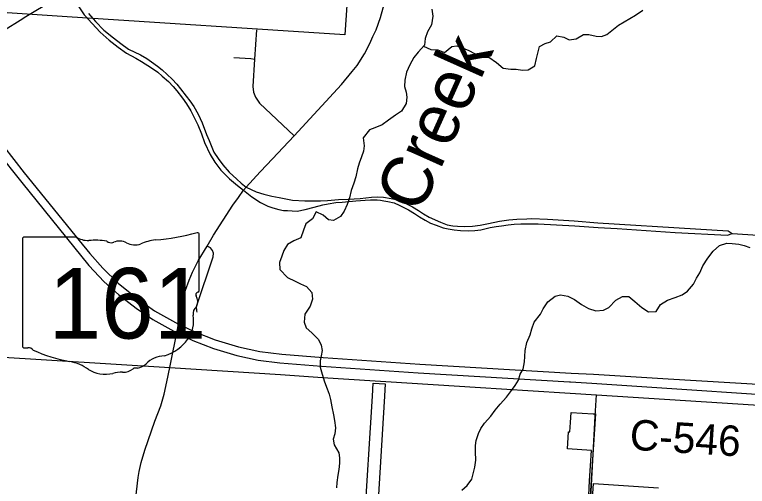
# Model space of a CAD drawing. Extents: x 0 to 91.3, y -0.7 to 22.
# Drawn here: x 3.152 to 4.519, y 17.345 to 18.226 of the extents above; entities that cross this region are included whole.
import ezdxf

# ---------------------------------------------------------------- set-up
doc = ezdxf.new("R2010")
doc.units = 0
for name, color, linetype in [('GM_X_City_Street', 7, 'Continuous'), ('GM_X_Corporation', 7, 'Continuous'), ('GM_X_County_Road', 7, 'Continuous'), ('GM_X_County_Road_Text', 7, 'Continuous'), ('GM_X_Minor_River', 7, 'Continuous'), ('GM_X_Minor_River_Text', 7, 'Continuous'), ('GM_X_State_Location', 7, 'Continuous'), ('GM_X_State_Route', 7, 'Continuous'), ('GM_X_State_Shield', 7, 'Continuous'), ('GM_X_US_Route', 7, 'Continuous')]:
    doc.layers.add(name, color=color, linetype=linetype)

msp = doc.modelspace()

# ---------------------------------------------------------------- linework, layer by layer
at = {"layer": 'GM_X_City_Street'}
for points in [[(3.2718, 18.24), (3.2817, 18.2251), (3.2962, 18.2089), (3.3114, 18.1927), (3.3284, 18.178), (3.3448, 18.1647), (3.3608, 18.1536), (3.378, 18.1446), (3.3883, 18.1384), (3.4075, 18.1265), (3.4188, 18.118), (3.4272, 18.1109), (3.4388, 18.1008), (3.4476, 18.0916), (3.4546, 18.0832), (3.4653, 18.0695), (3.4726, 18.0588), (3.4806, 18.0463), (3.4857, 18.0358), (3.4937, 18.0201), (3.5006, 18.0032), (3.5061, 17.9868), (3.5166, 17.9646), (3.5256, 17.95), (3.5364, 17.9355), (3.553, 17.9189), (3.5677, 17.9069), (3.5786, 17.8977)], [(3.2897, 18.2275), (3.3029, 18.2131), (3.3181, 18.1969), (3.3362, 18.1826), (3.35, 18.1718), (3.3644, 18.1611), (3.3866, 18.1503), (3.3982, 18.1436), (3.4073, 18.1373), (3.4185, 18.1294), (3.4268, 18.1227), (3.4455, 18.105), (3.4543, 18.0958), (3.4613, 18.0874), (3.472, 18.0737), (3.479, 18.0648), (3.4859, 18.0544), (3.494, 18.0396), (3.5017, 18.0234), (3.5099, 18.0018), (3.5148, 17.9906), (3.5233, 17.9688), (3.5318, 17.9573), (3.5405, 17.9453), (3.5523, 17.9317), (3.5661, 17.9183), (3.5744, 17.9111), (3.584, 17.9037), (3.6025, 17.895), (3.6167, 17.8905), (3.6318, 17.8869), (3.6456, 17.8842), (3.6704, 17.8795), (3.6933, 17.8781), (3.7102, 17.8777), (3.7224, 17.8781), (3.7358, 17.8785), (3.7563, 17.8802), (3.7741, 17.881), (3.7963, 17.8822), (3.8178, 17.8848), (3.8294, 17.8856), (3.8398, 17.8848), (3.854, 17.8822), (3.8637, 17.8803), (3.8768, 17.8757), (3.8941, 17.8665), (3.9053, 17.8602), (3.9148, 17.8538), (3.9252, 17.8477), (3.946, 17.8381), (3.9588, 17.8334), (3.9696, 17.8314), (3.9779, 17.8308), (3.9909, 17.8302), (4.0059, 17.8304), (4.0205, 17.8324), (4.036, 17.8355), (4.0561, 17.8397), (4.0738, 17.8422), (4.089, 17.8436), (4.1071, 17.8442), (4.1166, 17.8448), (4.1457, 17.8436), (4.1959, 17.8407), (4.2397, 17.8371), (4.4221, 17.8257), (4.4827, 17.8218), (4.4901, 17.8172)], [(3.6031, 18.1974), (3.5993, 18.1423), (3.5965, 18.0917), (3.5975, 18.0808), (3.6013, 18.0714), (3.6087, 18.0605), (3.6733, 17.9996)], [(3.5606, 18.1459), (3.5926, 18.1436), (3.5993, 18.1423)], [(3.5786, 17.8977), (3.5944, 17.8855), (3.6104, 17.8748), (3.6242, 17.868), (3.6335, 17.8647), (3.645, 17.8617), (3.6537, 17.8601), (3.6606, 17.8596), (3.6696, 17.8592), (3.6787, 17.8588), (3.694, 17.8617), (3.7107, 17.8662), (3.7271, 17.8704), (3.7367, 17.8723), (3.7512, 17.8748), (3.7626, 17.8756), (3.7883, 17.8781), (3.806, 17.8791), (3.8158, 17.8796), (3.8279, 17.8796), (3.8341, 17.8789), (3.8403, 17.8782), (3.8479, 17.8769), (3.8597, 17.8742), (3.869, 17.8701), (3.8863, 17.8609), (3.8975, 17.8546), (3.907, 17.8482), (3.9174, 17.8421), (3.9274, 17.8363), (3.9381, 17.8324), (3.951, 17.8278), (3.9605, 17.8255), (3.9718, 17.8236), (3.9834, 17.8224), (3.9989, 17.8218), (4.0106, 17.8224), (4.0218, 17.824), (4.0392, 17.8279), (4.0502, 17.83), (4.0602, 17.8315), (4.0728, 17.8331), (4.0836, 17.8341), (4.0963, 17.835), (4.1109, 17.8353), (4.1283, 17.8353), (4.1971, 17.8311), (4.2402, 17.8283), (4.2759, 17.826), (4.3843, 17.8191), (4.4819, 17.8141), (4.4901, 17.8172)], [(4.4901, 17.8172), (4.6159, 17.8088), (4.6734, 17.8048), (4.7564, 17.7996)]]:
    msp.add_lwpolyline(points, dxfattribs=at)
at = {"layer": 'GM_X_Corporation'}
msp.add_lwpolyline([(3.8019, 18.6958), (3.7678, 18.1877), (3.2499, 18.2218), (2.7457, 18.2558), (2.7736, 18.7721)], close=True, dxfattribs=at)
for points in [[(3.8037, 17.2665), (3.8193, 17.5135), (3.8209, 17.5377), (3.8322, 17.5369), (3.8433, 17.5362), (3.8419, 17.5135), (3.8279, 17.2882)], [(4.2227, 17.3281), (4.2244, 17.3548), (4.2262, 17.3833), (4.2281, 17.4116), (4.1832, 17.4146), (4.1853, 17.4468), (4.1878, 17.4466), (4.189, 17.4643), (4.1903, 17.4827), (4.2308, 17.4802), (4.2353, 17.48), (4.2258, 17.3279)], [(4.2275, 17.285), (4.2317, 17.3498), (4.3527, 17.3419)]]:
    msp.add_lwpolyline(points, dxfattribs=at)
at = {"layer": 'GM_X_County_Road'}
for p, q in [((3.6476, 17.5534), (3.7262, 17.5483)), ((3.7262, 17.5483), (3.8244, 17.542)), ((3.8244, 17.542), (3.8441, 17.5408)), ((3.8441, 17.5408), (4.0209, 17.5295)), ((4.0209, 17.5295), (4.0602, 17.527)), ((4.0602, 17.527), (4.0701, 17.5263)), ((4.0701, 17.5263), (4.1094, 17.5238)), ((4.1094, 17.5238), (4.188, 17.5188)), ((4.235, 17.4759), (4.2371, 17.5157))]:
    msp.add_line(p, q, dxfattribs=at)
for points in [[(3.6222, 17.9453), (3.6733, 17.9996), (3.7616, 18.0953), (3.7814, 18.1194), (3.7906, 18.1309), (3.8043, 18.1522), (3.8145, 18.1715), (3.8203, 18.1847), (3.8262, 18.1972), (3.8345, 18.2206), (3.846, 18.2638), (3.8752, 18.3822), (3.908, 18.5219), (3.9227, 18.5819), (3.9334, 18.627), (3.9497, 18.6887)], [(3.4432, 17.5763), (3.4545, 17.6317), (3.4576, 17.6479), (3.4634, 17.6779), (3.4708, 17.7113), (3.4773, 17.73), (3.4838, 17.745), (3.4941, 17.7661), (3.511, 17.7932), (3.5229, 17.8138), (3.5587, 17.8699), (3.5694, 17.8844), (3.5786, 17.8977), (3.584, 17.9037), (3.6098, 17.9322), (3.6222, 17.9453)], [(3.4923, 17.6701), (3.4916, 17.6728), (3.4912, 17.6809), (3.5224, 17.7736), (3.5226, 17.7805), (3.5211, 17.7853), (3.5173, 17.7899), (3.511, 17.7932)], [(2.7141, 17.6125), (2.7707, 17.6087), (3.4412, 17.5665), (3.6476, 17.5534)], [(3.3762, 17.3079), (3.3826, 17.361), (3.3844, 17.3728), (3.3881, 17.3893), (3.3947, 17.4123), (3.4133, 17.4666), (3.4243, 17.4954), (3.4308, 17.5171), (3.4361, 17.5397), (3.4412, 17.5665), (3.4432, 17.5763)], [(4.188, 17.5188), (4.2371, 17.5157), (4.5695, 17.4947), (4.592, 17.4929), (4.6804, 17.4873)], [(4.2269, 17.3269), (4.2276, 17.3349), (4.235, 17.4759)]]:
    msp.add_lwpolyline(points, dxfattribs=at)
at = {"layer": 'GM_X_Minor_River'}
for points in [[(3.93, 18.2361), (3.9322, 18.2225), (3.9298, 18.2069), (3.9218, 18.1937), (3.9179, 18.1812), (3.9163, 18.1687), (3.9049, 18.1558), (3.8968, 18.1456), (3.8888, 18.132), (3.8826, 18.1184), (3.8799, 18.1036), (3.8794, 18.0915), (3.8824, 18.0808), (3.8838, 18.0713), (3.8822, 18.0596), (3.8734, 18.0452), (3.8624, 18.0377), (3.8494, 18.0287), (3.8376, 18.02), (3.8239, 18.014), (3.814, 18.0106), (3.8021, 17.9959), (3.8036, 17.9807), (3.8028, 17.9709), (3.7989, 17.9599), (3.7946, 17.9481), (3.7915, 17.9379), (3.7884, 17.9228), (3.7845, 17.911), (3.7795, 17.897), (3.7764, 17.8837), (3.7725, 17.8712), (3.7668, 17.8587), (3.7599, 17.8485), (3.7465, 17.8414), (3.7371, 17.8426), (3.7272, 17.851), (3.7144, 17.8572), (3.7075, 17.8443), (3.6953, 17.8353), (3.6906, 17.8231), (3.6856, 17.8088), (3.673, 17.8035), (3.6609, 17.7964), (3.6543, 17.7854), (3.6501, 17.7748), (3.6462, 17.7627), (3.6469, 17.7498), (3.6609, 17.7349), (3.6749, 17.728), (3.6854, 17.723), (3.6964, 17.718), (3.7062, 17.7069), (3.7077, 17.6944), (3.703, 17.6815), (3.6934, 17.6664), (3.6918, 17.6512), (3.6959, 17.6406), (3.7061, 17.6314), (3.7186, 17.6188), (3.7234, 17.6082), (3.7253, 17.5983), (3.7237, 17.5888), (3.7221, 17.5793), (3.7217, 17.5676), (3.7258, 17.5542), (3.7299, 17.5402), (3.7347, 17.5269), (3.7384, 17.517), (3.741, 17.5071), (3.7436, 17.4934), (3.7465, 17.4782), (3.7488, 17.468), (3.7502, 17.4543), (3.7494, 17.4429), (3.7459, 17.4331), (3.7477, 17.422), (3.7564, 17.4076), (3.7582, 17.3981), (3.7581, 17.3878), (3.7565, 17.3761), (3.7549, 17.3655), (3.753, 17.3518), (3.7525, 17.3419)], [(3.9146, 18.1668), (3.928, 18.1603), (3.9413, 18.1602), (3.9538, 18.1548), (3.9672, 18.1661), (3.977, 18.1672), (3.9869, 18.1637), (3.9982, 18.1591), (4.0107, 18.1522), (4.0236, 18.146), (4.0365, 18.146), (4.0505, 18.1364), (4.0633, 18.1257), (4.0777, 18.1241), (4.0876, 18.124), (4.0993, 18.1221), (4.11, 18.1224), (4.1222, 18.1303), (4.1253, 18.1439), (4.1284, 18.156), (4.1311, 18.1663), (4.1418, 18.1719), (4.1513, 18.1749), (4.1631, 18.1862), (4.1764, 18.1838), (4.1862, 18.1788), (4.1995, 18.1807), (4.2132, 18.1885), (4.2231, 18.1885), (4.2367, 18.1854), (4.2466, 18.1846), (4.2565, 18.1887), (4.266, 18.1958), (4.2782, 18.206), (4.2889, 18.2124), (4.2992, 18.2184), (4.3099, 18.2244), (4.3236, 18.2342)], [(3.9859, 17.3379), (3.9958, 17.3462), (4.0046, 17.3583), (4.0081, 17.3704), (4.0105, 17.3806), (4.0121, 17.3939), (4.0114, 17.4091), (4.0119, 17.4209), (4.0131, 17.4303), (4.0173, 17.4432), (4.0215, 17.4531), (4.0284, 17.4629), (4.0399, 17.4761), (4.0483, 17.4871), (4.0575, 17.4984), (4.0697, 17.5112), (4.077, 17.521), (4.0858, 17.5331), (4.0916, 17.543), (4.0947, 17.554), (4.1004, 17.5638), (4.1028, 17.5774), (4.1036, 17.5873), (4.1044, 17.5983), (4.1072, 17.6131), (4.1133, 17.6275), (4.1164, 17.6388), (4.1211, 17.6513), (4.1326, 17.6661), (4.1379, 17.6763), (4.1467, 17.6891), (4.1605, 17.6997), (4.17, 17.7023), (4.1836, 17.6999), (4.1961, 17.6934), (4.2093, 17.6846), (4.2226, 17.6769), (4.2358, 17.6727), (4.2503, 17.6737), (4.2605, 17.679), (4.2735, 17.6926), (4.2861, 17.6993), (4.2975, 17.6996), (4.3088, 17.6901), (4.3216, 17.6786), (4.3345, 17.6706), (4.3485, 17.6712), (4.3566, 17.6841), (4.3695, 17.6924), (4.384, 17.6976), (4.3973, 17.7025), (4.4072, 17.7092), (4.4183, 17.7221), (4.4241, 17.7334), (4.4298, 17.7433), (4.4356, 17.7565), (4.4448, 17.7712), (4.4547, 17.7837), (4.467, 17.7946), (4.4806, 17.7987), (4.4905, 17.7983), (4.5027, 17.7971), (4.5125, 17.7944), (4.5231, 17.7909)]]:
    msp.add_lwpolyline(points, dxfattribs=at)
at = {"layer": 'GM_X_State_Route'}
for p, q in [((4.2316, 17.554), (4.3709, 17.5457)), ((4.2287, 17.5374), (4.3685, 17.528))]:
    msp.add_line(p, q, dxfattribs=at)
for points in [[(2.8069, 18.2433), (2.8463, 18.2248), (2.861, 18.2175), (2.8955, 18.1979), (2.9278, 18.1775), (2.9626, 18.1534), (3.0059, 18.1177), (3.0269, 18.0986), (3.0497, 18.0763), (3.0703, 18.0541), (3.0936, 18.0267), (3.1309, 17.9799), (3.1699, 17.9304), (3.2723, 17.8036), (3.2921, 17.7795), (3.3166, 17.7521), (3.3451, 17.7242), (3.3799, 17.696), (3.413, 17.6724), (3.4576, 17.6479), (3.4647, 17.6445)], [(2.9789, 18.1194), (2.9918, 18.1088), (3.0113, 18.0915), (3.0344, 18.0696), (3.0545, 18.0483), (3.0776, 18.0218), (3.1082, 17.9831), (3.1181, 17.9709), (3.1651, 17.9123), (3.2903, 17.7575), (3.3188, 17.727), (3.3458, 17.7031), (3.3783, 17.6776), (3.4099, 17.6561), (3.4545, 17.6317), (3.4571, 17.6304)], [(3.4647, 17.6445), (3.4878, 17.6331), (3.5262, 17.6184), (3.5696, 17.6055), (3.6093, 17.5967), (3.6501, 17.5915), (3.7275, 17.5855), (3.9079, 17.573), (4.1898, 17.5564), (4.2316, 17.554)], [(3.4571, 17.6304), (3.4846, 17.6169), (3.523, 17.6022), (3.5665, 17.5892), (3.6062, 17.5805), (3.6469, 17.5752), (3.7244, 17.5693), (3.9047, 17.5568), (4.1867, 17.5402), (4.1887, 17.5401), (4.2287, 17.5374)], [(4.3709, 17.5457), (4.549, 17.5351), (4.7393, 17.5249)], [(4.3685, 17.528), (4.5543, 17.5156), (4.7383, 17.5089)]]:
    msp.add_lwpolyline(points, dxfattribs=at)
at = {"layer": 'GM_X_State_Shield'}
for p, q in [((3.2664, 17.8103), (3.1699, 17.8103)), ((3.4963, 17.7105), (3.4963, 17.8152)), ((3.1667, 17.8068), (3.1667, 17.6067)), ((3.4962, 17.7106), (3.4963, 17.7105))]:
    msp.add_line(p, q, dxfattribs=at)
for centre, major_axis, start_param, end_param in [((3.1705, 17.8072), (0.00382, 0), 1.712693, 3.28349), ((3.2894, 17.8335), (0.037, 0), 4.042523, 4.731795), ((3.3789, 18.0831), (0.3495, 0), 4.814394, 5.042369), ((3.4926, 17.8156), (0.00367, 0), 6.141152, 7.989035), ((3.3017, 17.6979), (0.133, 0), 1.404758, 1.657858), ((3.3319, 17.8083), (0.0107, 0), 3.836095, 5.185415), ((3.3476, 17.7851), (0.0222, 0), 0.950623, 2.079405), ((3.3762, 17.8169), (0.0267, 0), 4.081561, 5.145723), ((3.4234, 17.7491), (0.0703, 0), 1.699011, 2.107814), ((3.4954, 17.7028), (0.00568, 0), 1.883978, 3.671073), ((3.4593, 17.6896), (0.0341, 0), 5.934695, 6.695948), ((3.4923, 17.7101), (0.00393, 0), 5.05454, 6.418171), ((3.5094, 17.6667), (0.0248, 0), 2.387724, 3.262537), ((3.3984, 17.6534), (0.0874, 0), 5.101752, 6.440018), ((3.1705, 17.6063), (0.00385, 0), 3.00124, 4.508301), ((3.1711, 17.6267), (0.0294, 0), 4.665946, 4.897461), ((3.1771, 17.5951), (0.0106, 0), 0.519207, 1.627899), ((3.3109, 17.7749), (0.2524, 0), 4.195997, 4.488961), ((3.2357, 17.5168), (0.079, 0), 0.823519, 1.323587), ((3.4353, 17.5505), (0.0479, 0), 1.647645, 2.488434), ((3.3537, 17.5792), (0.0267, 0), 4.691044, 5.507374), ((3.3778, 17.5598), (0.00752, 0), 1.147584, 2.315152), ((3.3746, 17.5873), (0.0282, 0), 4.937069, 5.64225), ((3.3211, 17.5942), (0.0501, 0), 4.026481, 4.996735), ((3.35, 17.525), (0.0412, 0), 1.495662, 1.94098)]:
    msp.add_ellipse(centre, major_axis=major_axis, ratio=0.8, start_param=start_param, end_param=end_param, dxfattribs=at)
at = {"layer": 'GM_X_US_Route'}
for points in [[(3.1671, 18.2187), (3.1697, 18.2203), (3.2266, 18.255)], [(3.0286, 18.1321), (3.0651, 18.1551), (3.0905, 18.1709), (3.1671, 18.2187)]]:
    msp.add_lwpolyline(points, dxfattribs=at)

# ---------------------------------------------------------------- texts
at = {"layer": 'GM_X_County_Road_Text'}
msp.add_text('C-546', height=0.05682, rotation=356.4235, dxfattribs=at).set_placement((4.2981, 17.4134))
at = {"layer": 'GM_X_Minor_River_Text'}
msp.add_text('Creek', height=0.0947, rotation=65.8737, dxfattribs=at).set_placement((3.9083, 17.8511))
at = {"layer": 'GM_X_State_Location'}
for s in ['s', 'r']:
    msp.add_text(s, height=0.000189, dxfattribs=at).set_placement((3.3278, 17.6934))
msp.add_text('161', height=0.000189, rotation=0, dxfattribs=at).set_placement((3.2609, 17.6797))
at = {"layer": 'GM_X_State_Shield'}
msp.add_text('161', height=0.13184, dxfattribs=at).set_placement((3.2152, 17.6208))

doc.saveas('drawing.dxf')
